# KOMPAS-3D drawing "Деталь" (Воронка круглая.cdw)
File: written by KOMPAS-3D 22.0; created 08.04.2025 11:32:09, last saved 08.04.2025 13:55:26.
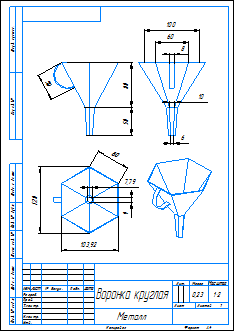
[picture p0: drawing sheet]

Sheet 1: A4, portrait

Document properties: Автор: Admin; Масса: 0.225513; Полное имя файла: Воронка круглая.m3d

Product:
- Body: Тело 8
    Масса: 0.195689
- Body: Тело 10
    Масса: 0.007182
- Part/product: Деталь
    Масса: 0.197153

Title block, sheet 1: Наименование: Воронка круглая; Материал: Металл; Масса: 0,23; Количество листов документа: 1; Форматы листов документа: A4; stored path: D:\28.11.2016\Абилимпикс\2025\Воронка квадратная.cdw

Views: Вид 1, Спереди, Проекционный вид 2, Проекционный вид 3, Проекционный вид 4
Referenced files in D:\28.11.2016\Абилимпикс\2025\: Воронка квадратная.m3d, Воронка круглая.m3d
Dimensions and other numbers on the sheet: 80; 50; 100; 8; 6; 10; 60; 7,79; 9; 103,92; 120; 1:2; 1; 0,23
